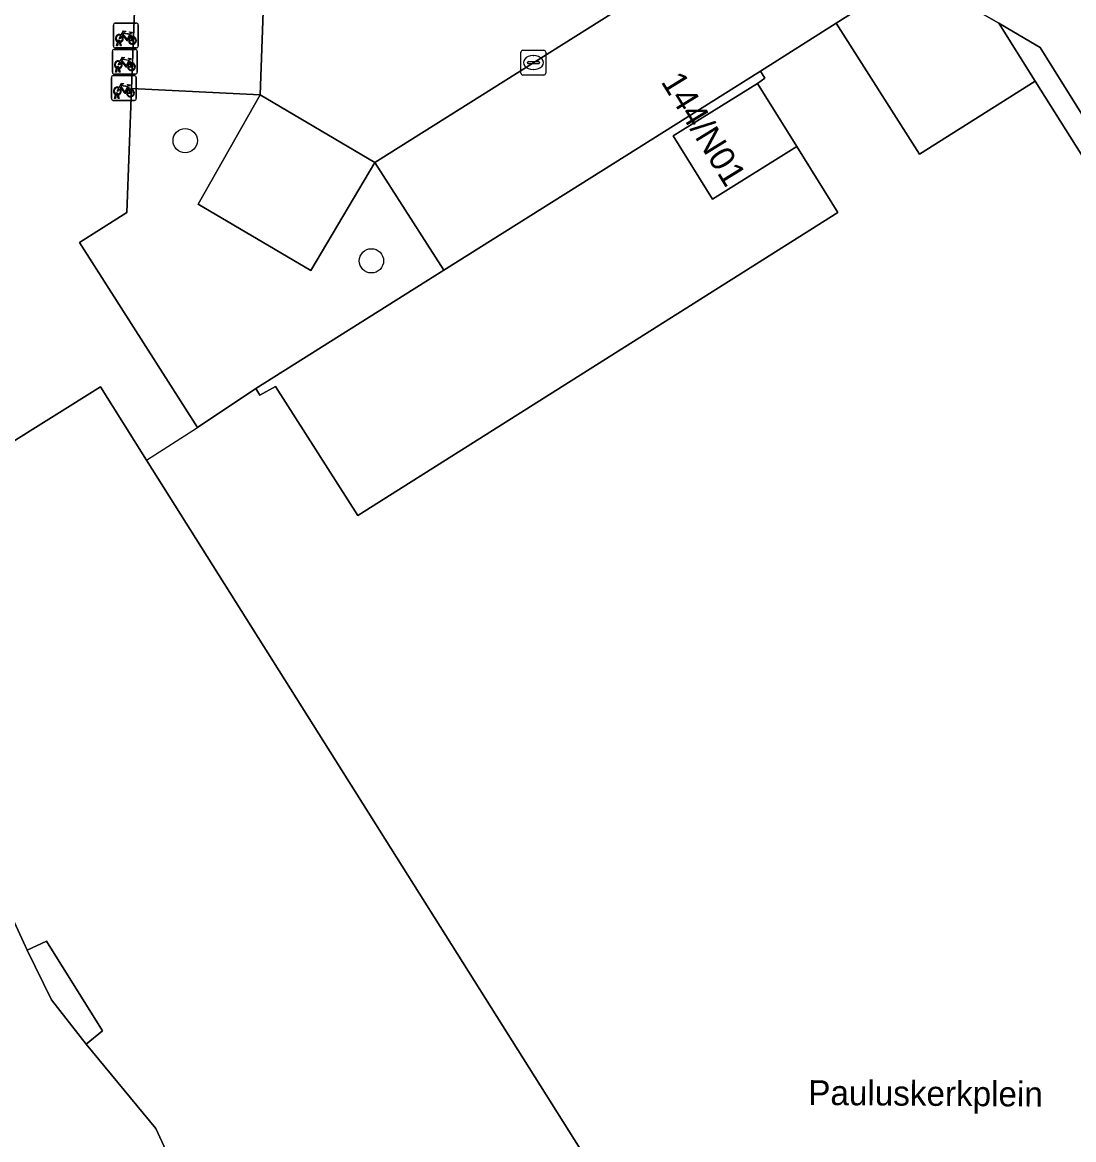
# Model space of a CAD drawing. Extents: x 160023 to 161302, y 384750 to 385707.
# Drawn here: x 160270.66 to 160312.97, y 384939.39 to 384984.38 of the extents above; entities that cross this region are included whole.
import ezdxf

# ---------------------------------------------------------------- set-up
doc = ezdxf.new("R2010")
doc.units = 0
for name, color, linetype in [('IMGEO_Boom', 7, 'Continuous'), ('IMGEO_Erf', 7, 'Continuous'), ('IMGEO_Fietsenrek', 7, 'Continuous'), ('IMGEO_Grasland_overig', 7, 'Continuous'), ('IMGEO_Groenvoorziening', 7, 'Continuous'), ('IMGEO_Haag', 7, 'Continuous'), ('IMGEO_Hek', 7, 'Continuous'), ('IMGEO_Kolk', 7, 'Continuous'), ('IMGEO_Openbare_ruimte_label', 7, 'Continuous'), ('IMGEO_Pand', 7, 'Continuous'), ('IMGEO_Pand_nummerreeks', 7, 'Continuous'), ('IMGEO_Parkeervlak_open', 7, 'Continuous'), ('IMGEO_Rijbaan_lokaal_open', 7, 'Continuous'), ('IMGEO_Voetpad_open', 7, 'Continuous')]:
    doc.layers.add(name, color=color, linetype=linetype)

msp = doc.modelspace()

# ---------------------------------------------------------------- linework, layer by layer
at = {"layer": 'IMGEO_Boom'}
for centre in [(160277.211, 384979.622), (160284.707, 384974.78)]:
    msp.add_circle(centre, 0.489, dxfattribs=at)
at = {"layer": 'IMGEO_Erf'}
for points in [[(160319.088, 384969.858), (160311.42, 384982.022), (160306.764, 384979.072), (160303.418, 384984.353), (160300.363, 384982.417), (160300.539, 384982.138), (160300.242, 384981.924), (160301.828, 384979.379), (160303.483, 384976.724), (160284.162, 384964.531), (160280.843, 384969.723), (160280.209, 384969.368), (160280.056, 384969.64), (160277.707, 384968.074), (160272.954, 384975.52), (160274.864, 384976.731), (160275.049, 384981.723), (160275.627, 384996.537)], [(160234.054, 384993.171), (160245.351, 384975.085), (160252.88, 384963.007), (160259.491, 384967.128), (160262.299, 384962.624), (160263.984, 384964.064), (160263.836, 384964.253), (160268.96, 384968.505), (160269.964, 384967.297), (160273.8, 384969.701), (160275.654, 384966.755), (160321.243, 384894.325), (160329.612, 384881.079), (160331.889, 384879.95), (160336.787, 384880.403), (160344.076, 384881.104), (160348.95, 384881.561), (160350.96, 384883.052), (160354.249, 384891.334), (160367.44, 384886.086), (160372.439, 384884.099)]]:
    msp.add_lwpolyline(points, dxfattribs=at)
at = {"layer": 'IMGEO_Fietsenrek'}
for p, q in [((160274.322, 384983.43), (160274.322, 384984.271)), ((160274.322, 384984.271), (160274.322, 384983.43)), ((160274.397, 384984.355), (160275.238, 384984.355)), ((160275.238, 384984.355), (160274.397, 384984.355)), ((160275.322, 384984.28), (160275.322, 384983.439)), ((160275.322, 384983.439), (160275.322, 384984.28)), ((160274.449, 384983.439), (160274.488, 384983.599)), ((160274.518, 384983.587), (160274.483, 384983.439)), ((160274.56, 384983.611), (160274.559, 384983.615)), ((160274.601, 384983.439), (160274.567, 384983.581)), ((160274.591, 384983.622), (160274.592, 384983.615)), ((160274.599, 384983.585), (160274.634, 384983.439)), ((160275.009, 384983.904), (160275.045, 384983.809)), ((160274.28, 384982.372), (160274.28, 384983.213)), ((160274.28, 384983.213), (160274.28, 384982.372)), ((160274.355, 384983.297), (160275.196, 384983.297)), ((160275.196, 384983.297), (160274.355, 384983.297)), ((160275.247, 384983.355), (160274.406, 384983.355)), ((160274.406, 384983.355), (160275.247, 384983.355)), ((160274.483, 384983.439), (160274.449, 384983.439)), ((160274.634, 384983.439), (160274.601, 384983.439)), ((160275.28, 384983.222), (160275.28, 384982.381)), ((160275.28, 384982.381), (160275.28, 384983.222)), ((160274.967, 384982.846), (160275.003, 384982.751)), ((160274.314, 384982.239), (160275.155, 384982.239)), ((160275.155, 384982.239), (160274.314, 384982.239)), ((160275.205, 384982.297), (160274.364, 384982.297)), ((160274.364, 384982.297), (160275.205, 384982.297)), ((160274.407, 384982.381), (160274.446, 384982.541)), ((160274.441, 384982.381), (160274.407, 384982.381)), ((160274.476, 384982.529), (160274.441, 384982.381)), ((160274.518, 384982.553), (160274.517, 384982.557)), ((160274.559, 384982.381), (160274.525, 384982.523)), ((160274.549, 384982.564), (160274.55, 384982.557)), ((160274.557, 384982.527), (160274.592, 384982.381)), ((160274.592, 384982.381), (160274.559, 384982.381)), ((160275.239, 384982.164), (160275.239, 384981.323)), ((160275.239, 384981.323), (160275.239, 384982.164)), ((160274.239, 384981.314), (160274.239, 384982.155)), ((160274.239, 384982.155), (160274.239, 384981.314)), ((160274.926, 384981.788), (160274.962, 384981.693)), ((160274.366, 384981.323), (160274.405, 384981.483)), ((160274.4, 384981.323), (160274.366, 384981.323)), ((160274.435, 384981.471), (160274.4, 384981.323)), ((160274.477, 384981.495), (160274.476, 384981.499)), ((160274.518, 384981.323), (160274.484, 384981.465)), ((160274.508, 384981.506), (160274.509, 384981.499)), ((160274.516, 384981.469), (160274.551, 384981.323)), ((160274.551, 384981.323), (160274.518, 384981.323)), ((160275.164, 384981.239), (160274.323, 384981.239)), ((160274.323, 384981.239), (160275.164, 384981.239))]:
    msp.add_line(p, q, dxfattribs=at)
for points in [[(160274.635, 384983.881), (160274.73, 384984.045), (160274.816, 384984.031), (160274.818, 384984.022), (160274.762, 384984.011), (160274.735, 384983.966), (160274.991, 384983.925)], [(160274.991, 384983.925), (160275.016, 384983.974), (160275.01, 384983.978), (160274.987, 384983.982), (160274.975, 384983.989), (160274.974, 384983.992), (160274.976, 384983.997), (160275.071, 384983.982), (160275.073, 384983.972), (160275.063, 384983.959), (160275.051, 384983.953), (160275.037, 384983.959), (160275.009, 384983.904)], [(160274.656, 384983.829), (160274.604, 384983.739), (160274.564, 384983.714), (160274.565, 384983.761), (160274.62, 384983.855)], [(160274.931, 384983.637), (160274.881, 384983.637), (160274.69, 384983.888), (160274.671, 384983.856)], [(160274.978, 384983.9), (160274.721, 384983.941), (160274.704, 384983.912), (160274.871, 384983.692), (160274.978, 384983.9)], [(160275.026, 384983.802), (160274.996, 384983.879), (160274.887, 384983.661), (160274.93, 384983.661)], [(160274.96, 384983.661), (160275.08, 384983.66), (160275.036, 384983.774)], [(160275.056, 384983.781), (160275.111, 384983.636), (160274.961, 384983.636)], [(160274.614, 384982.771), (160274.562, 384982.681), (160274.522, 384982.656), (160274.523, 384982.703), (160274.578, 384982.797)], [(160274.593, 384982.823), (160274.688, 384982.987), (160274.774, 384982.973), (160274.776, 384982.964), (160274.72, 384982.953), (160274.693, 384982.908), (160274.949, 384982.867)], [(160274.889, 384982.579), (160274.839, 384982.579), (160274.648, 384982.83), (160274.629, 384982.798)], [(160274.936, 384982.842), (160274.679, 384982.883), (160274.662, 384982.854), (160274.829, 384982.634), (160274.936, 384982.842)], [(160274.984, 384982.744), (160274.954, 384982.821), (160274.845, 384982.603), (160274.888, 384982.603)], [(160274.918, 384982.603), (160275.038, 384982.602), (160274.994, 384982.716)], [(160275.014, 384982.723), (160275.069, 384982.578), (160274.919, 384982.578)], [(160274.949, 384982.867), (160274.974, 384982.916), (160274.968, 384982.92), (160274.945, 384982.924), (160274.933, 384982.931), (160274.932, 384982.934), (160274.934, 384982.939), (160275.029, 384982.924), (160275.031, 384982.914), (160275.021, 384982.901), (160275.009, 384982.895), (160274.995, 384982.901), (160274.967, 384982.846)], [(160274.573, 384981.713), (160274.521, 384981.623), (160274.481, 384981.598), (160274.482, 384981.645), (160274.537, 384981.739)], [(160274.552, 384981.765), (160274.647, 384981.929), (160274.733, 384981.915), (160274.735, 384981.906), (160274.679, 384981.895), (160274.652, 384981.85), (160274.908, 384981.809)], [(160274.848, 384981.521), (160274.798, 384981.521), (160274.607, 384981.772), (160274.588, 384981.74)], [(160274.895, 384981.784), (160274.638, 384981.825), (160274.621, 384981.796), (160274.788, 384981.576), (160274.895, 384981.784)], [(160274.943, 384981.686), (160274.913, 384981.763), (160274.804, 384981.545), (160274.847, 384981.545)], [(160274.908, 384981.809), (160274.933, 384981.858), (160274.927, 384981.862), (160274.904, 384981.866), (160274.892, 384981.873), (160274.891, 384981.876), (160274.893, 384981.881), (160274.988, 384981.866), (160274.99, 384981.856), (160274.98, 384981.843), (160274.968, 384981.837), (160274.954, 384981.843), (160274.926, 384981.788)], [(160274.877, 384981.545), (160274.997, 384981.544), (160274.953, 384981.658)], [(160274.973, 384981.665), (160275.028, 384981.52), (160274.878, 384981.52)]]:
    msp.add_lwpolyline(points, dxfattribs=at)
for centre, radius, start, end in [((160274.4, 384984.277), 0.0779, 92.4484, 184.2845), ((160274.4, 384984.277), 0.0779, 92.4484, 184.2845), ((160275.244, 384984.277), 0.0779, 2.4484, 94.2845), ((160275.244, 384984.277), 0.0779, 2.4484, 94.2845), ((160274.562, 384983.74), 0.159, 62.6766, 242.1369), ((160274.562, 384983.74), 0.129, 63.3192, 238.903), ((160274.542, 384983.611), 0.0499, 12.8025, 158.6934), ((160274.562, 384983.74), 0.159, 253.9967, 271.7867), ((160274.542, 384983.611), 0.0174, 12.8025, 163.4502), ((160274.562, 384983.74), 0.129, 253.415, 269.0204), ((160274.562, 384983.74), 0.129, 283.6043, 43.4302), ((160274.562, 384983.74), 0.159, 283.5766, 46.6042), ((160275.089, 384983.656), 0.159, 113.3408, 178.3217), ((160275.089, 384983.656), 0.159, 187.0065, 105.7708), ((160275.089, 384983.656), 0.129, 113.923, 177.9556), ((160275.089, 384983.656), 0.129, 188.6715, 104.5883), ((160274.358, 384983.219), 0.0779, 92.4484, 184.2845), ((160274.358, 384983.219), 0.0779, 92.4484, 184.2845), ((160274.4, 384983.433), 0.0779, 182.4484, 274.2845), ((160274.4, 384983.433), 0.0779, 182.4484, 274.2845), ((160275.202, 384983.219), 0.0779, 2.4484, 94.2845), ((160275.202, 384983.219), 0.0779, 2.4484, 94.2845), ((160275.244, 384983.433), 0.0779, 272.4484, 4.2845), ((160275.244, 384983.433), 0.0779, 272.4484, 4.2845), ((160274.52, 384982.682), 0.159, 62.6766, 242.1369), ((160274.52, 384982.682), 0.129, 63.3192, 238.903), ((160274.52, 384982.682), 0.129, 283.6043, 43.4302), ((160274.52, 384982.682), 0.159, 283.5766, 46.6042), ((160275.047, 384982.598), 0.159, 113.3408, 178.3217), ((160275.047, 384982.598), 0.159, 187.0065, 105.7708), ((160275.047, 384982.598), 0.129, 113.923, 177.9556), ((160275.047, 384982.598), 0.129, 188.6715, 104.5883), ((160274.317, 384982.161), 0.0779, 92.4484, 184.2845), ((160274.317, 384982.161), 0.0779, 92.4484, 184.2845), ((160274.358, 384982.375), 0.0779, 182.4484, 274.2845), ((160274.358, 384982.375), 0.0779, 182.4484, 274.2845), ((160274.5, 384982.553), 0.0499, 12.8025, 158.6934), ((160274.52, 384982.682), 0.159, 253.9967, 271.7867), ((160274.5, 384982.553), 0.0174, 12.8025, 163.4502), ((160274.52, 384982.682), 0.129, 253.415, 269.0204), ((160275.161, 384982.161), 0.0779, 2.4484, 94.2845), ((160275.161, 384982.161), 0.0779, 2.4484, 94.2845), ((160275.202, 384982.375), 0.0779, 272.4484, 4.2845), ((160275.202, 384982.375), 0.0779, 272.4484, 4.2845), ((160274.479, 384981.624), 0.159, 62.6766, 242.1369), ((160274.479, 384981.624), 0.129, 63.3192, 238.903), ((160274.479, 384981.624), 0.129, 283.6043, 43.4302), ((160274.479, 384981.624), 0.159, 283.5766, 46.6042), ((160274.317, 384981.317), 0.0779, 182.4484, 274.2845), ((160274.317, 384981.317), 0.0779, 182.4484, 274.2845), ((160274.459, 384981.495), 0.0499, 12.8025, 158.6934), ((160274.479, 384981.624), 0.159, 253.9967, 271.7867), ((160274.459, 384981.495), 0.0174, 12.8025, 163.4502), ((160274.479, 384981.624), 0.129, 253.415, 269.0204), ((160275.006, 384981.54), 0.159, 113.3408, 178.3217), ((160275.006, 384981.54), 0.159, 187.0065, 105.7708), ((160275.006, 384981.54), 0.129, 113.923, 177.9556), ((160275.006, 384981.54), 0.129, 188.6715, 104.5883), ((160275.161, 384981.317), 0.0779, 272.4484, 4.2845), ((160275.161, 384981.317), 0.0779, 272.4484, 4.2845)]:
    msp.add_arc(centre, radius, start, end, dxfattribs=at)
at = {"layer": 'IMGEO_Grasland_overig'}
msp.add_lwpolyline([(160270.855, 384947.017), (160271.835, 384945.016), (160273.221, 384943.233), (160273.88, 384943.778), (160271.634, 384947.385)], close=True, dxfattribs=at)
at = {"layer": 'IMGEO_Groenvoorziening'}
for points in [[(160303.418, 384984.353), (160306.764, 384979.072), (160311.42, 384982.022), (160309.954, 384984.347), (160306.528, 384986.323)], [(160287.618, 384974.398), (160284.846, 384978.742), (160282.264, 384974.394), (160277.734, 384977.059), (160280.224, 384981.464), (160275.049, 384981.723), (160274.864, 384976.731), (160272.954, 384975.52), (160277.707, 384968.074), (160280.056, 384969.64)]]:
    msp.add_lwpolyline(points, close=True, dxfattribs=at)
msp.add_lwpolyline([(160277.869, 384935.855), (160276.031, 384939.845), (160273.221, 384943.233), (160271.835, 384945.016), (160270.855, 384947.017), (160269.007, 384951.005), (160266.217, 384954.389), (160264.593, 384956.365), (160266.284, 384957.777), (160264.426, 384960.712), (160263.776, 384960.298), (160262.299, 384962.624), (160259.491, 384967.128), (160252.88, 384963.007), (160256.796, 384956.724), (160259.963, 384951.655), (160268.235, 384938.344)], dxfattribs=at)
at = {"layer": 'IMGEO_Haag'}
msp.add_lwpolyline([(160303.418, 384984.353), (160306.764, 384979.072), (160311.42, 384982.022), (160309.954, 384984.347), (160306.528, 384986.323)], close=True, dxfattribs=at)
at = {"layer": 'IMGEO_Hek'}
for points in [[(160311.42, 384982.022), (160309.954, 384984.347)], [(160319.088, 384969.858), (160311.42, 384982.022)], [(160275.654, 384966.755), (160277.707, 384968.074)]]:
    msp.add_lwpolyline(points, dxfattribs=at)
at = {"layer": 'IMGEO_Kolk'}
for p, q in [((160290.725, 384982.337), (160290.725, 384983.189)), ((160290.8, 384983.263), (160291.652, 384983.263)), ((160291.726, 384983.189), (160291.726, 384982.337)), ((160290.984, 384982.757), (160290.984, 384982.769)), ((160291.422, 384982.72), (160291.024, 384982.72)), ((160291.027, 384982.806), (160291.425, 384982.806)), ((160291.213, 384983.043), (160291.238, 384983.043)), ((160291.468, 384982.769), (160291.468, 384982.757)), ((160291.652, 384982.263), (160290.8, 384982.263)), ((160291.236, 384982.483), (160291.211, 384982.483))]:
    msp.add_line(p, q, dxfattribs=at)
for points in [[(160290.725, 384982.337), (160290.725, 384983.189)], [(160290.8, 384983.263), (160291.652, 384983.263)], [(160291.726, 384983.189), (160291.726, 384982.337)], [(160291.652, 384982.263), (160290.8, 384982.263)]]:
    msp.add_lwpolyline(points, dxfattribs=at)
for centre, radius, start, end in [((160290.802, 384983.187), 0.0765, 91.552, 178.448), ((160290.802, 384983.187), 0.0765, 91.552, 178.448), ((160291.65, 384983.187), 0.0765, 1.552, 88.448), ((160291.65, 384983.187), 0.0765, 1.552, 88.448), ((160291.024, 384982.766), 0.0403, 85.8775, 175.7526), ((160291.021, 384982.756), 0.0366, 178.938, 274.7102), ((160291.425, 384982.763), 0.043, 264.8664, 352.4533), ((160291.429, 384982.768), 0.0386, 1.7309, 96.639), ((160290.802, 384982.339), 0.0765, 181.552, 268.448), ((160290.802, 384982.339), 0.0765, 181.552, 268.448), ((160291.65, 384982.339), 0.0765, 271.552, 358.448), ((160291.65, 384982.339), 0.0765, 271.552, 358.448)]:
    msp.add_arc(centre, radius, start, end, dxfattribs=at)
for centre, major_axis, ratio, start_param, end_param in [((160291.212, 384982.763), (-0.387, 0.002), 0.722429, 4.712389, 7.853982), ((160291.237, 384982.763), (-0.39, 0.002), 0.717154, 1.570796, 4.712389)]:
    msp.add_ellipse(centre, major_axis=major_axis, ratio=ratio, start_param=start_param, end_param=end_param, dxfattribs=at)
at = {"layer": 'IMGEO_Pand'}
for points in [[(160300.242, 384981.924), (160300.539, 384982.138), (160300.363, 384982.417), (160287.618, 384974.398), (160280.056, 384969.64), (160280.209, 384969.368), (160280.843, 384969.723), (160284.162, 384964.531), (160303.483, 384976.724), (160301.828, 384979.379), (160298.435, 384977.264), (160296.849, 384979.811)], [(160296.849, 384979.811), (160298.435, 384977.264), (160301.828, 384979.379), (160300.242, 384981.924)]]:
    msp.add_lwpolyline(points, close=True, dxfattribs=at)
msp.add_lwpolyline([(160321.243, 384894.325), (160275.654, 384966.755), (160273.8, 384969.701), (160269.964, 384967.297), (160268.96, 384968.505), (160263.836, 384964.253), (160263.984, 384964.064), (160264.196, 384963.794), (160262.974, 384963.02), (160264.426, 384960.712), (160266.284, 384957.777), (160267.679, 384955.591), (160266.217, 384954.389), (160269.007, 384951.005), (160270.855, 384947.017), (160271.634, 384947.385), (160273.88, 384943.778), (160273.221, 384943.233), (160276.031, 384939.845), (160277.869, 384935.855)], dxfattribs=at)
at = {"layer": 'IMGEO_Parkeervlak_open'}
for points in [[(160280.762, 384996.321), (160275.627, 384996.537), (160275.049, 384981.723), (160280.224, 384981.464)], [(160306.528, 384986.323), (160301.494, 384989.225), (160284.846, 384978.742), (160287.618, 384974.398), (160300.363, 384982.417), (160303.418, 384984.353)], [(160284.846, 384978.742), (160280.224, 384981.464), (160277.734, 384977.059), (160282.264, 384974.394)]]:
    msp.add_lwpolyline(points, close=True, dxfattribs=at)
at = {"layer": 'IMGEO_Rijbaan_lokaal_open'}
for points in [[(160294.807, 384993.08), (160297.902, 384991.296), (160301.494, 384989.225), (160306.528, 384986.323), (160309.954, 384984.347), (160310.546, 384984.006), (160311.625, 384983.376), (160316.844, 384975.01), (160323.19, 384978.952), (160325.802, 384974.741), (160331.674, 384978.392), (160329.942, 384979.419), (160329.09, 384979.915), (160311.924, 384989.805), (160310.878, 384990.412), (160299.637, 384996.89), (160299.342, 384997.013), (160288.826, 385003.17)], [(160284.795, 384998.891), (160282.916, 385000), (160280.916, 385001.181), (160280.879, 385000), (160280.762, 384996.321), (160280.224, 384981.464), (160284.846, 384978.742), (160301.494, 384989.225), (160297.902, 384991.296)]]:
    msp.add_lwpolyline(points, dxfattribs=at)
at = {"layer": 'IMGEO_Voetpad_open'}
msp.add_lwpolyline([(160311.625, 384983.376), (160310.546, 384984.006), (160309.954, 384984.347), (160311.42, 384982.022), (160319.088, 384969.858), (160326.105, 384974.218), (160332.272, 384978.049), (160331.674, 384978.392), (160325.802, 384974.741), (160319.457, 384970.81), (160316.844, 384975.01)], close=True, dxfattribs=at)

# ---------------------------------------------------------------- texts
at = {"layer": 'IMGEO_Openbare_ruimte_label'}
msp.add_text('Pauluskerkplein', height=1, rotation=359.5989, dxfattribs=at).set_placement((160302.286, 384940.787))
at = {"layer": 'IMGEO_Pand_nummerreeks'}
msp.add_text('144/N01', height=1, rotation=301.627, dxfattribs=at).set_placement((160296.337, 384981.994))

doc.saveas('drawing.dxf')
